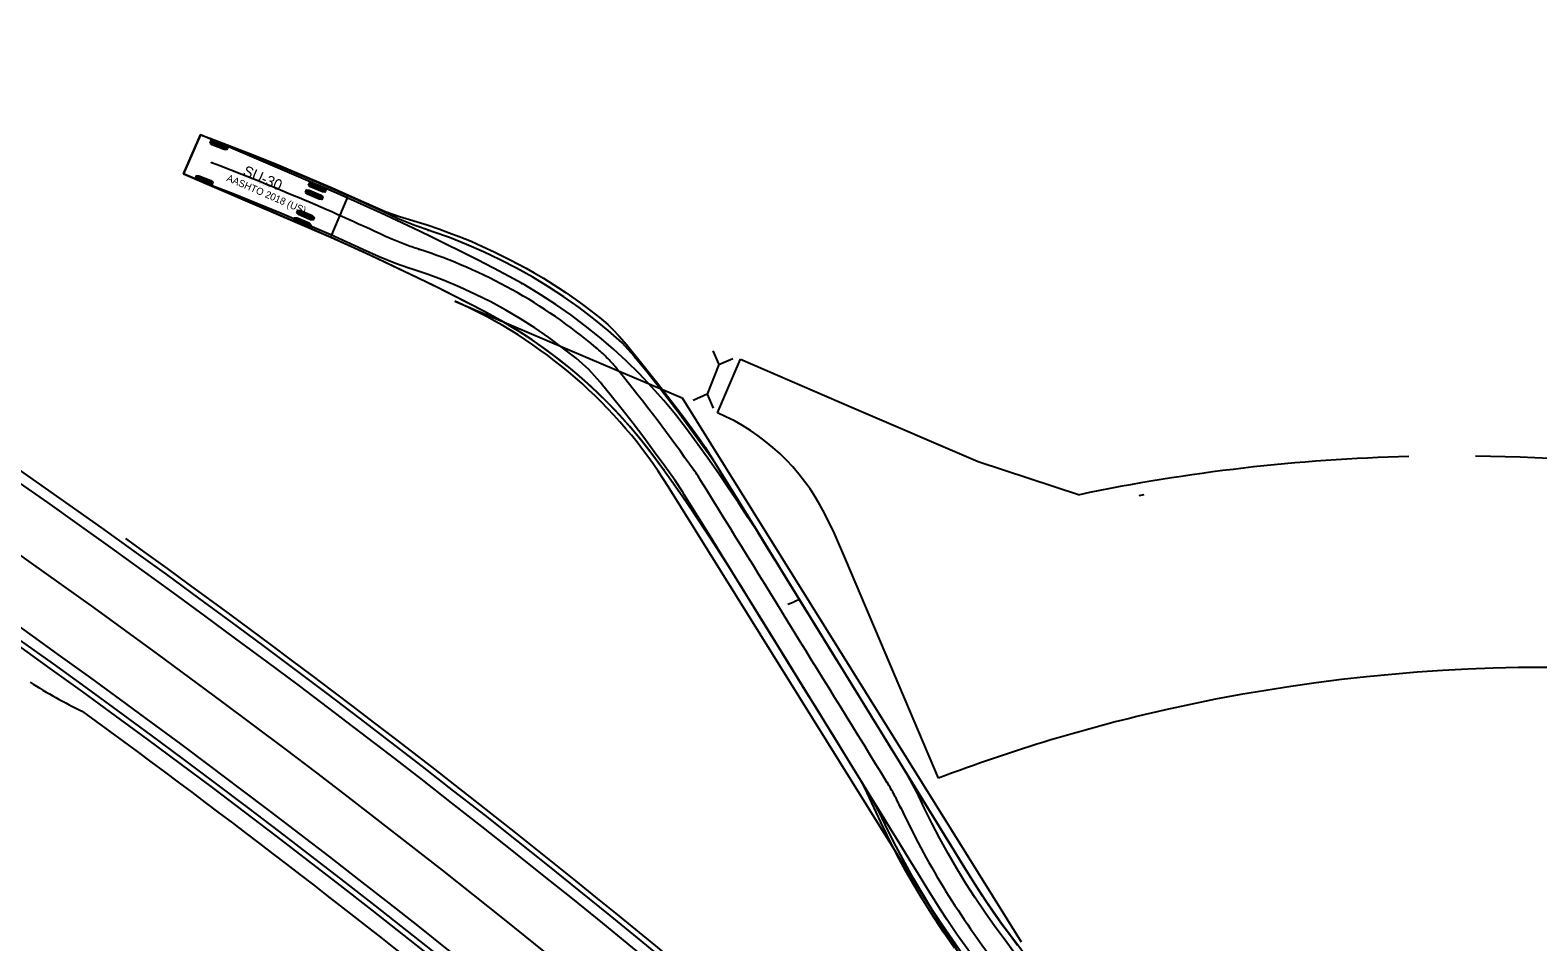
# Model space of a CAD drawing. Extents: x 1600240 to 1604759, y 285789 to 289704.
# Drawn here: x 1601036.7 to 1601319, y 286716.1 to 286886.8 of the extents above; entities that cross this region are included whole.
import ezdxf

# ---------------------------------------------------------------- set-up
doc = ezdxf.new("R2010")
doc.units = 0
for name, color, linetype in [('GE_P_Alignment', 7, 'Continuous'), ('MT_P_Cells', 7, 'Continuous'), ('MT_P_CL_Double_Solid', 7, 'Continuous'), ('MT_P_Drums', 7, 'Continuous'), ('MT_P_Edge_Line', 7, 'Continuous'), ('MT_P_Temp_Road', 7, 'Continuous'), ('MT_P_Work_Area', 7, 'Continuous'), ('MT_X_CL_Double_Solid', 7, 'Continuous'), ('MT_X_Edge_Line', 7, 'Continuous'), ('PM_X_Edge_Line', 7, 'Continuous')]:
    doc.layers.add(name, color=color, linetype=linetype)

msp = doc.modelspace()

# ---------------------------------------------------------------- linework, layer by layer
at = {"layer": 'GE_P_Alignment'}
msp.add_arc((1599925.32, 285220.33), 1921, 44.01664, 58.20662, dxfattribs=at)
at = {"layer": 'MT_P_Cells'}
for p, q in [((1601165.65, 286824.16), (1601163.44, 286818.59)), ((1601164.53, 286826.76), (1601165.65, 286824.16)), ((1601165.65, 286824.16), (1601168.25, 286825.29)), ((1601163.44, 286818.59), (1601160.85, 286817.46)), ((1601163.44, 286818.59), (1601164.56, 286815.99))]:
    msp.add_line(p, q, dxfattribs=at)
at = {"layer": 'MT_P_CL_Double_Solid'}
for p, q in [((1601068.61, 286867.21), (1601065.45, 286859.86)), ((1601096.17, 286855.37), (1601068.61, 286867.21)), ((1601070.48, 286865.66), (1601073.59, 286864.47)), ((1601070.55, 286865.85), (1601073.66, 286864.66)), ((1601070.62, 286866.05), (1601073.74, 286864.86)), ((1601065.45, 286859.86), (1601093.02, 286848.02)), ((1601065.45, 286859.86), (1601065.45, 286859.86)), ((1601067.68, 286859.06), (1601070.79, 286857.87)), ((1601067.75, 286859.25), (1601070.87, 286858.06)), ((1601067.83, 286859.45), (1601070.94, 286858.26)), ((1601088.97, 286858.01), (1601092.03, 286856.7)), ((1601089.05, 286858.2), (1601092.11, 286856.89)), ((1601088.29, 286856.44), (1601091.35, 286855.13)), ((1601088.37, 286856.63), (1601091.44, 286855.32)), ((1601088.46, 286856.83), (1601091.52, 286855.51)), ((1601088.88, 286857.82), (1601091.95, 286856.5)), ((1601093.02, 286848.02), (1601096.17, 286855.37)), ((1601086.65, 286852.61), (1601089.71, 286851.3)), ((1601086.73, 286852.81), (1601089.79, 286851.49)), ((1601086.81, 286853), (1601089.87, 286851.68)), ((1601086.05, 286851.24), (1601089.12, 286849.92)), ((1601086.14, 286851.43), (1601089.2, 286850.11)), ((1601086.22, 286851.62), (1601089.28, 286850.3)), ((1601244.31, 286799.65), (1601245.26, 286799.81))]:
    msp.add_line(p, q, dxfattribs=at)
for points in [[(1601209.76, 286714.9), (1601207.72, 286717.86), (1601205.39, 286721.42), (1601203.32, 286724.76), (1601201.98, 286727.02), (1601200.68, 286729.31), (1601199.42, 286731.62), (1601198.34, 286733.67), (1601197.14, 286736.04), (1601195.97, 286738.44), (1601193.44, 286743.95), (1601192.84, 286745.14), (1601192.2, 286746.3), (1601174.8, 286774.53), (1601166.82, 286787.41), (1601163.98, 286791.82), (1601160.89, 286796.46), (1601157.91, 286800.78), (1601154.86, 286805.06), (1601152.71, 286807.97), (1601150.88, 286810.3), (1601148.99, 286812.55), (1601147.04, 286814.74), (1601145.92, 286815.93), (1601144.56, 286817.33), (1601143.16, 286818.7), (1601141.74, 286820.04), (1601140.54, 286821.13), (1601139.06, 286822.42), (1601137.56, 286823.67), (1601136.03, 286824.89), (1601134.74, 286825.88), (1601133.16, 286827.05), (1601131.56, 286828.18), (1601129.93, 286829.27), (1601128.56, 286830.16), (1601126.89, 286831.19), (1601125.48, 286832.02), (1601123.78, 286832.99), (1601121.76, 286834.08), (1601118.86, 286835.59), (1601112.13, 286839), (1601105.59, 286842.18), (1601099.27, 286845.15), (1601094.42, 286847.35), (1601089.56, 286849.5), (1601065.45, 286859.86), (1601068.61, 286867.21), (1601070.38, 286866.55), (1601074.44, 286865), (1601078.48, 286863.41), (1601082.51, 286861.79), (1601086.21, 286860.26), (1601093.28, 286857.24), (1601097.56, 286855.35), (1601101.82, 286853.43), (1601103.36, 286852.78), (1601104.62, 286852.31), (1601105.88, 286851.87), (1601111.03, 286850.3), (1601113.26, 286849.55), (1601115.17, 286848.86), (1601117.07, 286848.13), (1601119.27, 286847.24), (1601121.44, 286846.29), (1601123.6, 286845.3), (1601126.62, 286843.79), (1601129.6, 286842.19), (1601131.07, 286841.35), (1601132.81, 286840.31), (1601135.66, 286838.51), (1601137.07, 286837.58), (1601138.73, 286836.43), (1601140.37, 286835.24), (1601141.71, 286834.23), (1601143.31, 286832.99), (1601144.09, 286832.35), (1601144.85, 286831.68), (1601145.83, 286830.74), (1601147.01, 286829.49), (1601148.35, 286827.9), (1601151.19, 286824.41), (1601154.18, 286820.65), (1601156.68, 286817.41), (1601159.13, 286814.17), (1601162.13, 286810.09), (1601163.09, 286808.69), (1601172.8, 286793.01), (1601175.85, 286788.14), (1601178.49, 286783.8), (1601196.56, 286754.5), (1601212.64, 286728.37), (1601214.08, 286726.08), (1601215.57, 286723.81), (1601216.9, 286721.85), (1601218.45, 286719.64), (1601220.03, 286717.49), (1601221.57, 286715.46)], [(1601111.29, 286849.32), (1601108.73, 286850.21), (1601105.65, 286851.47), (1601102.61, 286852.87), (1601099.55, 286854.27), (1601096.49, 286855.64), (1601093.41, 286856.99), (1601090.32, 286858.33), (1601087.23, 286859.64), (1601084.13, 286860.93), (1601081.01, 286862.2), (1601077.89, 286863.45), (1601074.76, 286864.68), (1601072.26, 286865.65)], [(1601107.64, 286842.23), (1601105.15, 286843.07), (1601102.05, 286844.32), (1601099.03, 286845.72), (1601096.03, 286847.09), (1601093.01, 286848.44), (1601089.98, 286849.77), (1601086.94, 286851.08), (1601083.9, 286852.37), (1601080.84, 286853.64), (1601077.78, 286854.89), (1601074.71, 286856.11), (1601071.63, 286857.32), (1601069.16, 286858.27)], [(1601128.81, 286839.33), (1601126.43, 286840.65), (1601123.44, 286842.23), (1601120.45, 286843.76), (1601117.46, 286845.28), (1601114.45, 286846.77), (1601111.43, 286848.25), (1601108.41, 286849.7), (1601105.37, 286851.14), (1601102.32, 286852.55), (1601099.27, 286853.95), (1601096.2, 286855.32), (1601093.13, 286856.67), (1601090.66, 286857.74)], [(1601124.84, 286832.39), (1601122.63, 286833.61), (1601119.75, 286835.13), (1601116.82, 286836.64), (1601113.87, 286838.13), (1601110.91, 286839.6), (1601107.94, 286841.05), (1601104.96, 286842.48), (1601101.97, 286843.89), (1601098.98, 286845.29), (1601095.97, 286846.66), (1601092.95, 286848.01), (1601089.93, 286849.34), (1601087.5, 286850.39)], [(1601109.46, 286845.78), (1601109.14, 286845.88), (1601108.83, 286845.98), (1601108.51, 286846.09), (1601108.19, 286846.2), (1601107.88, 286846.3), (1601107.56, 286846.42), (1601107.25, 286846.53), (1601106.94, 286846.64), (1601106.63, 286846.76), (1601106.31, 286846.88), (1601106, 286847), (1601105.69, 286847.12), (1601105.38, 286847.24), (1601105.07, 286847.37), (1601104.77, 286847.5), (1601104.46, 286847.63), (1601104.15, 286847.76), (1601103.85, 286847.89), (1601103.55, 286848.03), (1601103.24, 286848.17)], [(1601150.07, 286825.39), (1601149.86, 286825.66), (1601147.53, 286828.23), (1601144.94, 286830.57), (1601142.25, 286832.75), (1601139.49, 286834.84), (1601136.66, 286836.83), (1601133.77, 286838.72), (1601130.81, 286840.52), (1601127.8, 286842.21), (1601124.72, 286843.8), (1601121.6, 286845.29), (1601118.43, 286846.67), (1601115.21, 286847.94), (1601111.95, 286849.1), (1601111.29, 286849.32)], [(1601143.64, 286820.64), (1601143.44, 286820.89), (1601141.29, 286823.25), (1601138.92, 286825.34), (1601136.41, 286827.32), (1601133.84, 286829.21), (1601131.21, 286831.02), (1601128.51, 286832.73), (1601125.76, 286834.35), (1601122.96, 286835.88), (1601120.1, 286837.31), (1601117.2, 286838.64), (1601114.26, 286839.88), (1601111.27, 286841.01), (1601108.25, 286842.04), (1601107.64, 286842.23)], [(1601161.79, 286809.12), (1601161.6, 286809.4), (1601159.59, 286812.12), (1601157.52, 286814.81), (1601155.35, 286817.42), (1601153.11, 286819.96), (1601150.77, 286822.42), (1601148.36, 286824.8), (1601145.86, 286827.1), (1601143.29, 286829.31), (1601140.65, 286831.43), (1601137.93, 286833.47), (1601135.15, 286835.41), (1601132.31, 286837.25), (1601129.4, 286839), (1601128.81, 286839.33)], [(1601155.3, 286804.45), (1601155.11, 286804.72), (1601153.19, 286807.33), (1601151.26, 286809.82), (1601149.27, 286812.23), (1601147.2, 286814.56), (1601145.05, 286816.83), (1601142.83, 286819.02), (1601140.53, 286821.13), (1601138.17, 286823.17), (1601135.74, 286825.12), (1601133.24, 286826.99), (1601130.68, 286828.77), (1601128.06, 286830.47), (1601125.39, 286832.08), (1601124.84, 286832.39)], [(1601146.86, 286823.02), (1601146.65, 286823.27), (1601146.43, 286823.53), (1601146.22, 286823.78), (1601146, 286824.04), (1601145.78, 286824.29), (1601145.56, 286824.54), (1601145.33, 286824.78), (1601145.11, 286825.02), (1601144.88, 286825.27), (1601144.64, 286825.5), (1601144.41, 286825.74), (1601144.17, 286825.97), (1601143.93, 286826.21), (1601143.69, 286826.43), (1601143.44, 286826.66), (1601143.19, 286826.88), (1601142.94, 286827.1), (1601142.69, 286827.32)], [(1601165.69, 286804.5), (1601164.19, 286806.78), (1601162.22, 286809.53), (1601160.23, 286812.27), (1601158.2, 286814.99), (1601156.16, 286817.68), (1601154.08, 286820.36), (1601151.99, 286823.02), (1601150.07, 286825.39)], [(1601158.89, 286800.29), (1601157.45, 286802.46), (1601155.53, 286805.15), (1601153.57, 286807.83), (1601151.6, 286810.48), (1601149.59, 286813.11), (1601147.57, 286815.73), (1601145.51, 286818.32), (1601143.64, 286820.64)], [(1601176.21, 286787.48), (1601174.79, 286789.76), (1601172.99, 286792.62), (1601171.16, 286795.46), (1601169.3, 286798.29), (1601167.41, 286801.09), (1601165.5, 286803.88), (1601163.56, 286806.65), (1601161.79, 286809.12)], [(1601169.4, 286783.28), (1601168, 286785.53), (1601166.24, 286788.32), (1601164.45, 286791.1), (1601162.64, 286793.86), (1601160.79, 286796.6), (1601158.92, 286799.33), (1601157.03, 286802.03), (1601155.3, 286804.45)], [(1601162.29, 286802.39), (1601162.12, 286802.68), (1601161.94, 286802.96), (1601161.76, 286803.24), (1601161.57, 286803.52), (1601161.39, 286803.8), (1601161.2, 286804.07), (1601161.01, 286804.35)], [(1601203.12, 286743.21), (1601202.7, 286744.11), (1601201.12, 286747.07), (1601199.37, 286749.94), (1601197.62, 286752.78), (1601195.87, 286755.63), (1601194.12, 286758.47), (1601192.36, 286761.31), (1601190.61, 286764.15), (1601188.86, 286767), (1601187.11, 286769.84), (1601185.35, 286772.68), (1601183.6, 286775.52), (1601181.84, 286778.36), (1601180.09, 286781.21), (1601178.34, 286784.05), (1601176.58, 286786.89), (1601174.83, 286789.73), (1601173.07, 286792.57), (1601171.31, 286795.41), (1601169.56, 286798.25), (1601167.8, 286801.09), (1601166.04, 286803.93), (1601165.69, 286804.5)], [(1601196.28, 286739.09), (1601195.84, 286740), (1601194.28, 286742.92), (1601192.56, 286745.75), (1601190.8, 286748.59), (1601189.05, 286751.43), (1601187.3, 286754.27), (1601185.55, 286757.12), (1601183.8, 286759.96), (1601182.05, 286762.8), (1601180.29, 286765.64), (1601178.54, 286768.48), (1601176.79, 286771.32), (1601175.03, 286774.17), (1601173.28, 286777.01), (1601171.53, 286779.85), (1601169.77, 286782.69), (1601168.02, 286785.53), (1601166.26, 286788.37), (1601164.51, 286791.21), (1601162.75, 286794.05), (1601161, 286796.89), (1601159.24, 286799.72), (1601158.89, 286800.29)], [(1601213.84, 286726.46), (1601213.32, 286727.27), (1601211.59, 286730.06), (1601209.85, 286732.9), (1601208.1, 286735.75), (1601206.35, 286738.59), (1601204.6, 286741.43), (1601202.85, 286744.28), (1601201.1, 286747.12), (1601199.35, 286749.97), (1601197.59, 286752.81), (1601195.84, 286755.65), (1601194.09, 286758.5), (1601192.34, 286761.34), (1601190.59, 286764.18), (1601188.83, 286767.02), (1601187.08, 286769.86), (1601185.33, 286772.71), (1601183.57, 286775.55), (1601181.82, 286778.39), (1601180.07, 286781.23), (1601178.31, 286784.07), (1601176.56, 286786.91), (1601176.21, 286787.48)], [(1601207.1, 286722.15), (1601206.56, 286723), (1601204.78, 286725.87), (1601203.03, 286728.71), (1601201.28, 286731.55), (1601199.53, 286734.4), (1601197.78, 286737.24), (1601196.03, 286740.09), (1601194.28, 286742.93), (1601192.53, 286745.77), (1601190.78, 286748.61), (1601189.03, 286751.46), (1601187.28, 286754.3), (1601185.53, 286757.14), (1601183.78, 286759.98), (1601182.02, 286762.82), (1601180.27, 286765.66), (1601178.52, 286768.51), (1601176.77, 286771.35), (1601175.01, 286774.19), (1601173.26, 286777.03), (1601171.5, 286779.87), (1601169.75, 286782.71), (1601169.4, 286783.28)], [(1601199.7, 286741.15), (1601199.56, 286741.45), (1601199.41, 286741.75), (1601199.27, 286742.05), (1601199.12, 286742.35), (1601198.97, 286742.65), (1601198.82, 286742.95), (1601198.67, 286743.24), (1601198.51, 286743.54), (1601198.35, 286743.83), (1601198.19, 286744.12), (1601198.03, 286744.42), (1601197.87, 286744.71), (1601197.7, 286745), (1601197.53, 286745.28), (1601197.36, 286745.57), (1601197.19, 286745.85)], [(1601221.55, 286713.17), (1601221.18, 286713.71), (1601219.22, 286716.34), (1601217.31, 286718.94), (1601215.45, 286721.59), (1601213.65, 286724.28), (1601211.91, 286727.01), (1601210.22, 286729.77), (1601208.6, 286732.57), (1601207.04, 286735.4), (1601205.53, 286738.27), (1601204.09, 286741.16), (1601203.12, 286743.21)], [(1601215.81, 286707.64), (1601215.41, 286708.19), (1601213.37, 286710.89), (1601211.34, 286713.63), (1601209.37, 286716.41), (1601207.46, 286719.23), (1601205.61, 286722.08), (1601203.83, 286724.98), (1601202.1, 286727.92), (1601200.44, 286730.89), (1601198.84, 286733.9), (1601197.31, 286736.94), (1601196.28, 286739.09)], [(1601235.88, 286699.45), (1601235.42, 286699.89), (1601233.16, 286702.15), (1601230.94, 286704.46), (1601228.77, 286706.82), (1601226.65, 286709.23), (1601224.58, 286711.68), (1601222.57, 286714.18), (1601220.61, 286716.72), (1601218.71, 286719.29), (1601216.86, 286721.91), (1601215.06, 286724.57), (1601213.84, 286726.46)], [(1601230.34, 286693.68), (1601229.85, 286694.15), (1601227.45, 286696.54), (1601225.11, 286698.98), (1601222.83, 286701.47), (1601220.6, 286704), (1601218.42, 286706.59), (1601216.3, 286709.21), (1601214.23, 286711.89), (1601212.23, 286714.6), (1601210.28, 286717.36), (1601208.39, 286720.16), (1601207.1, 286722.15)]]:
    msp.add_lwpolyline(points, dxfattribs=at)
for points in [[(1601070.46, 286865.61), (1601070.64, 286866.09), (1601071.13, 286866.07), (1601073.38, 286865.22), (1601073.76, 286864.9), (1601073.57, 286864.42), (1601073.08, 286864.44), (1601070.84, 286865.3)], [(1601067.66, 286859.01), (1601067.84, 286859.5), (1601068.34, 286859.48), (1601070.58, 286858.62), (1601070.96, 286858.31), (1601070.77, 286857.82), (1601070.28, 286857.84), (1601068.04, 286858.7)], [(1601088.86, 286857.77), (1601089.07, 286858.25), (1601089.56, 286858.21), (1601091.76, 286857.26), (1601092.13, 286856.93), (1601091.93, 286856.46), (1601091.44, 286856.5), (1601089.23, 286857.45)], [(1601088.27, 286856.4), (1601088.48, 286856.87), (1601088.97, 286856.83), (1601091.17, 286855.88), (1601091.54, 286855.56), (1601091.33, 286855.08), (1601090.84, 286855.12), (1601088.64, 286856.07)], [(1601086.63, 286852.57), (1601086.83, 286853.04), (1601087.32, 286853), (1601089.53, 286852.06), (1601089.89, 286851.73), (1601089.69, 286851.25), (1601089.2, 286851.29), (1601086.99, 286852.24)], [(1601086.03, 286851.19), (1601086.24, 286851.67), (1601086.73, 286851.63), (1601088.94, 286850.68), (1601089.3, 286850.35), (1601089.1, 286849.87), (1601088.61, 286849.91), (1601086.4, 286850.86)]]:
    msp.add_lwpolyline(points, close=True, dxfattribs=at)
for centre in [(1601072.26, 286865.65), (1601070.71, 286861.96), (1601069.16, 286858.27), (1601090.66, 286857.74), (1601087.5, 286850.39), (1601103.24, 286848.17), (1601103.24, 286848.17), (1601111.29, 286849.32), (1601111.29, 286849.32), (1601109.46, 286845.78), (1601109.46, 286845.78), (1601107.64, 286842.23), (1601107.64, 286842.23), (1601128.81, 286839.33), (1601128.81, 286839.33), (1601124.84, 286832.39), (1601124.84, 286832.39), (1601142.69, 286827.32), (1601142.69, 286827.32), (1601150.07, 286825.39), (1601150.07, 286825.39), (1601146.86, 286823.02), (1601146.86, 286823.02), (1601143.64, 286820.64), (1601143.64, 286820.64), (1601161.79, 286809.12), (1601161.79, 286809.12), (1601155.3, 286804.45), (1601155.3, 286804.45), (1601161.01, 286804.35), (1601161.01, 286804.35), (1601165.69, 286804.5), (1601165.69, 286804.5), (1601162.29, 286802.39), (1601162.29, 286802.39), (1601158.89, 286800.29), (1601158.89, 286800.29), (1601176.21, 286787.48), (1601176.21, 286787.48), (1601169.4, 286783.28), (1601169.4, 286783.28), (1601197.19, 286745.85), (1601197.19, 286745.85), (1601203.12, 286743.21), (1601203.12, 286743.21), (1601199.7, 286741.15), (1601199.7, 286741.15), (1601196.28, 286739.09), (1601196.28, 286739.09), (1601213.84, 286726.46), (1601213.84, 286726.46), (1601207.1, 286722.15), (1601207.1, 286722.15)]:
    msp.add_circle(centre, 0.0417, dxfattribs=at)
for centre, radius, start, end in [((1600894.36, 286400.5), 494.01, 64.986, 69.0852), ((1601079.4, 286752.53), 97.97, 49.7623, 72.1339), ((1600880.19, 286606.14), 343.72, 35.2139, 39.1199), ((1575452.53, 270895.44), 30232.81, 31.619693, 31.745614), ((1601339.81, 286806.83), 154.74, 205.115, 217.5318)]:
    msp.add_arc(centre, radius, start, end, dxfattribs=at)
at = {"layer": 'MT_P_Drums'}
msp.add_line((1601212.88, 286710.24), (1601156.15, 286801.34), dxfattribs=at)
msp.add_lwpolyline([(1601116.22, 286836.05), (1601144.09, 286824.2), (1601158.78, 286817.94), (1601222.22, 286716.05)], dxfattribs=at)
for centre, radius, start, end in [((1599925.32, 285220.33), 1934, 44.01664, 58.20679), ((1599924.79, 285219.82), 1908.74, 44.01664, 58.51433), ((1601079.75, 286753.77), 90, 31.9095, 66.0973)]:
    msp.add_arc(centre, radius, start, end, dxfattribs=at)
at = {"layer": 'MT_P_Edge_Line'}
msp.add_arc((1599925.32, 285220.33), 1907, 44.01664, 58.51987, dxfattribs=at)
at = {"layer": 'MT_P_Temp_Road'}
msp.add_arc((1599925.32, 285220.33), 1921, 44.01664, 58.20662, dxfattribs=at)
at = {"layer": 'MT_P_Work_Area'}
for radius, start in [(1932, 44.01664), (1910, 44.35059)]:
    msp.add_arc((1599925.32, 285220.33), radius, start, 57.77229, dxfattribs=at)
at = {"layer": 'MT_X_CL_Double_Solid'}
msp.add_arc((1599925.32, 285220.33), 1935, 45.17115, 54.2946, dxfattribs=at)
at = {"layer": 'MT_X_Edge_Line'}
msp.add_arc((1602837.87, 287782.94), 1921, 229.7619, 229.7619, dxfattribs=at)
at = {"layer": 'PM_X_Edge_Line'}
for p, q in [((1601165.37, 286815.13), (1601169.7, 286825.17)), ((1601214.19, 286806.02), (1601233.16, 286799.79)), ((1601187.33, 286792.51), (1601185.42, 286796.31)), ((1601206.79, 286746.72), (1601189.42, 286787.59))]:
    msp.add_line(p, q, dxfattribs=at)
for points in [[(1601169.7, 286825.17), (1601190.49, 286816.21), (1601214.19, 286806.02)], [(1601189.42, 286787.59), (1601187.33, 286792.51), (1601187.33, 286792.51)]]:
    msp.add_lwpolyline(points, dxfattribs=at)
for centre, radius, start, end in [((1601149.68, 286778.33), 40, 26.7021, 66.9054), ((1601303.28, 286464.04), 343, 91.4134, 101.7963), ((1601303.03, 286462.27), 344.77, 74.5736, 89.2879), ((1601169.4, 286802.52), 25, 291.5811, 296.3486), ((1601320.92, 286440.5), 326.96, 75.9637, 102.6554), ((1601085.9, 286841.84), 91.5, 237.5008, 244.5495), ((1599883.72, 285167.79), 1971.01, 50.88416, 53.84415), ((1601320.97, 286444.58), 323, 102.8222, 110.7018)]:
    msp.add_arc(centre, radius, start, end, dxfattribs=at)

# ---------------------------------------------------------------- texts
at = {"layer": 'MT_P_CL_Double_Solid'}
for s, height, p in [('SU-30', 2, (1601076.41, 286859.68)), ('AASHTO 2018 (US)', 1.3333, (1601073.39, 286858.62)), ('(c) 2024 Transoft Solutions, Inc. All rights reserved.', 0.08, (1601079.29, 286858.23))]:
    msp.add_text(s, height=height, rotation=336.7458, dxfattribs=at).set_placement(p)

doc.saveas('drawing.dxf')
